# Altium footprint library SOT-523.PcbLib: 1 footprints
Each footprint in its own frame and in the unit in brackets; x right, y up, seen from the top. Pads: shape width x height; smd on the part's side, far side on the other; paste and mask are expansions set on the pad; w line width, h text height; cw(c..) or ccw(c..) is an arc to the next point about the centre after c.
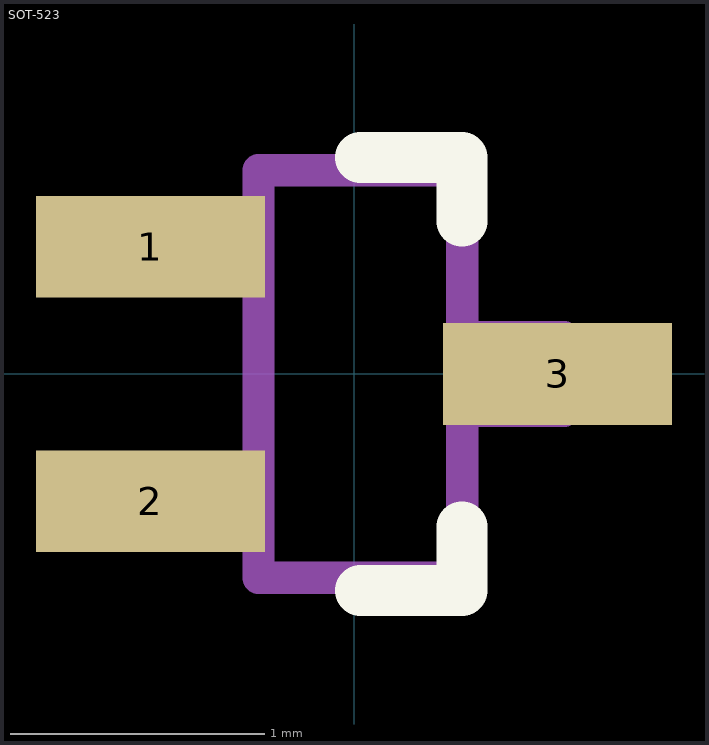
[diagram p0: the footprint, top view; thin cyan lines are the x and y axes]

## SOT-523 [mm] "From Diodes Inc datasheet component parameters"
height 0.9
pads (3):
  rect 0.9x0.4 smd: 1(-0.8,0.5) 2(-0.8,-0.5) 3(0.8,0)
Top Overlay:
  lines w0.2: 0.025,-0.85 0.425,-0.85 0.425,-0.6 ; 0.025,0.85 0.425,0.85 0.425,0.6
M5 Assembly Top:
  lines w0.127: -0.375,-0.6 -0.375,-0.4 ; -0.375,-0.6 -0.375,-0.788 -0.375,-0.8 0.425,-0.8 0.425,-0.788 0.425,-0.144 ; -0.375,-0.6 -0.5,-0.6 -0.514,-0.6 -0.538,-0.6 -0.775,-0.6 -0.775,-0.4 -0.538,-0.4 -0.514,-0.4 -0.5,-0.4 -0.375,-0.4 ; -0.375,-0.4 -0.375,0.4 ; -0.375,0.4 -0.375,0.6 ; -0.375,0.4 -0.5,0.4 -0.514,0.4 -0.538,0.4 -0.775,0.4 -0.775,0.6 -0.538,0.6 -0.514,0.6 -0.5,0.6 -0.375,0.6 ; -0.375,0.6 -0.375,0.787 -0.375,0.8 0.425,0.8 0.425,0.787 0.425,0.144 ; 0.425,-0.144 0.55,-0.144 0.564,-0.144 0.588,-0.144 0.825,-0.144 0.825,0.144 0.588,0.144 0.564,0.144 0.55,0.144 0.425,0.144 ; 0.425,-0.144 0.425,0.144
  text ".Designator" at -0.175,0.65 h0.36
3D body: height 0.79, standoff -0.01, extent -0.803,-0.8 0.797,0.8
